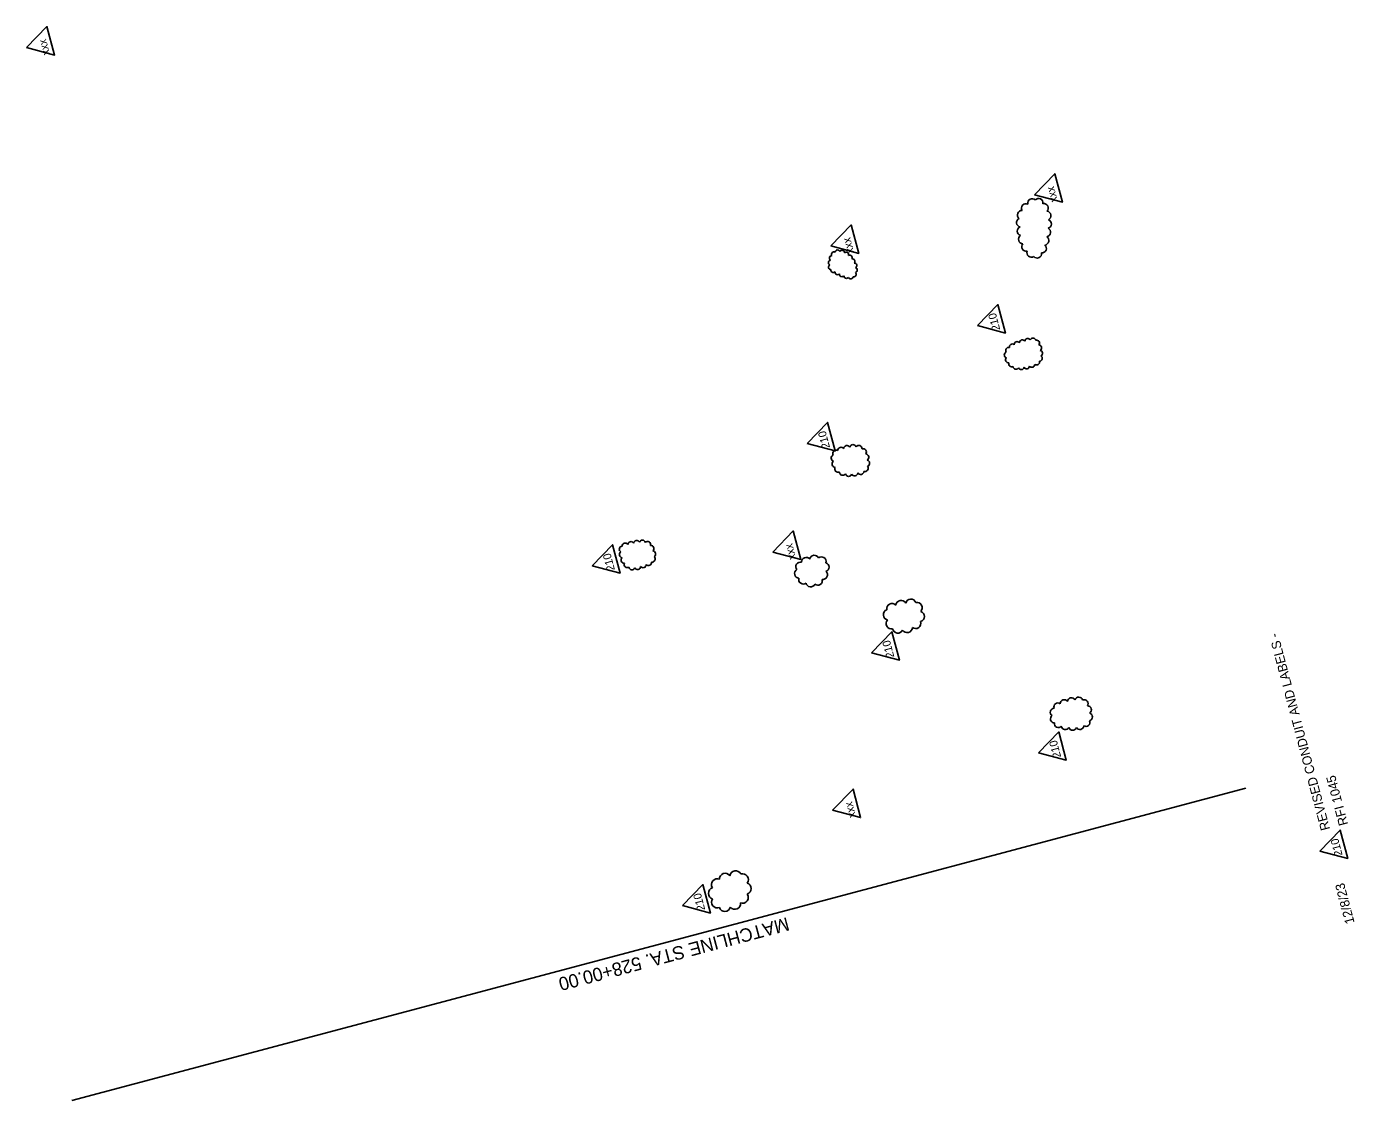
# Model space of a CAD drawing. Extents: x 930124 to 931163, y 628803 to 630086.
# Drawn here: x 930367 to 931163, y 628803 to 629446 of the extents above; entities that cross this region are included whole.
import ezdxf

# ---------------------------------------------------------------- set-up
doc = ezdxf.new("R2010")
doc.units = 0
for name, color, linetype in [('Cloud_dp', 7, 'Continuous'), ('MatchLines_dp', 7, 'Continuous'), ('TextMinor', 7, 'Continuous')]:
    doc.layers.add(name, color=color, linetype=linetype)

msp = doc.modelspace()

# ---------------------------------------------------------------- linework, layer by layer
at = {"layer": 'Cloud_dp'}
for points in [[(930366.73, 629433.4), (930383.48, 629428.93), (930378.95, 629445.99)], [(930970.88, 629345.22), (930987.64, 629340.76), (930983.1, 629357.81)], [(930848.77, 629314.6), (930865.53, 629310.13), (930860.99, 629327.19)], [(930936.68, 629266.85), (930953.44, 629262.39), (930948.9, 629279.45)], [(930834.69, 629196.2), (930851.44, 629191.74), (930846.91, 629208.8)], [(930813.99, 629131.2), (930830.75, 629126.74), (930826.21, 629143.8)], [(930705.73, 629122.9), (930722.49, 629118.44), (930717.95, 629135.5)], [(930873.21, 629070.79), (930889.97, 629066.32), (930885.43, 629083.38)], [(930973.23, 629010.87), (930989.98, 629006.4), (930985.45, 629023.46)], [(930849.92, 628976.57), (930866.67, 628972.11), (930862.14, 628989.17)], [(931141.9, 628952.04), (931158.66, 628947.58), (931154.12, 628964.64)], [(930759.86, 628919.33), (930776.62, 628914.86), (930772.08, 628931.92)]]:
    msp.add_lwpolyline(points, close=True, dxfattribs=at)
for centre, radius, start, end in [((930969.56, 629340.2), 2.69, 47.02622, 192.02622), ((930973.34, 629340.3), 2.69, 351.17918, 136.17918), ((930963.33, 629333.12), 2.69, 85.90866, 230.90866), ((930965.83, 629337.18), 2.69, 65.81449, 210.81449), ((930976.48, 629337.25), 2.69, 315.47406, 100.47406), ((930978.03, 629332.7), 2.69, 297.05766, 82.05766), ((930962.8, 629328.61), 2.69, 115.67642, 260.67642), ((930963.28, 629323.43), 2.69, 109.9098, 254.9098), ((930978.36, 629327.77), 2.69, 285.53496, 70.53496), ((930964.05, 629318.58), 2.69, 123.04285, 268.04285), ((930976.87, 629317.81), 2.69, 273.85274, 58.85274), ((930977.87, 629322.77), 2.69, 278.3399, 63.3399), ((930850.78, 629309.54), 1.51, 64.25659, 209.25659), ((930852.93, 629310.64), 1.51, 25.19628, 170.19628), ((930855.55, 629310.45), 1.51, 1.35126, 146.35126), ((930858.01, 629309.31), 1.51, 343.81258, 128.81258), ((930965.96, 629314.1), 2.69, 138.15829, 283.15829), ((930969.06, 629310.45), 2.69, 157.53748, 302.53748), ((930972.48, 629310.01), 2.69, 222.67057, 7.67057), ((930975.34, 629313.05), 2.69, 265.6604, 50.6604), ((930848.86, 629304.56), 1.51, 99.66415, 244.66415), ((930848.98, 629301.89), 1.51, 120.6446, 265.6446), ((930849.47, 629307.29), 1.51, 90.23348, 235.23348), ((930860.11, 629307.52), 1.51, 330.43389, 115.43389), ((930861.78, 629305.31), 1.51, 318.65228, 103.65228), ((930862.87, 629302.8), 1.51, 303.2417, 88.2417), ((930863.2, 629300.1), 1.51, 285.88168, 70.88168), ((930850.35, 629300.11), 1.51, 169.55406, 314.55406), ((930852.91, 629298.84), 1.51, 172.8068, 317.8068), ((930855.53, 629297.64), 1.51, 172.84611, 317.84611), ((930858.17, 629296.61), 1.51, 179.33238, 324.33238), ((930860.76, 629296.37), 1.51, 205.1875, 350.1875), ((930862.53, 629297.6), 1.51, 259.199, 44.199), ((930957.61, 629254.08), 1.75, 48.74386, 193.74386), ((930960.51, 629255.5), 1.75, 38.60674, 183.60674), ((930963.63, 629256.56), 1.75, 33.64007, 178.64007), ((930966.84, 629257.37), 1.75, 29.72414, 174.72414), ((930970, 629257.61), 1.75, 14.24363, 159.24363), ((930972.16, 629256.36), 1.75, 320.56938, 105.56938), ((930973.42, 629253.5), 1.75, 301.71008, 86.71008), ((930954.57, 629249.23), 1.75, 107.95728, 252.95728), ((930955.3, 629246.32), 1.75, 135.05486, 280.05486), ((930955.4, 629251.98), 1.75, 73.30566, 218.30566), ((930973.8, 629247.21), 1.75, 272.29497, 57.29497), ((930974.02, 629250.28), 1.75, 294.57143, 79.57143), ((930957.2, 629243.87), 1.75, 155.73325, 300.73325), ((930959.84, 629242.44), 1.75, 182.50447, 327.50447), ((930962.93, 629242.2), 1.75, 203.4699, 348.4699), ((930966.16, 629242.73), 1.75, 210.06027, 355.06027), ((930969.33, 629243.6), 1.75, 215.86298, 0.86298), ((930972.19, 629244.99), 1.75, 230.80152, 15.80152), ((930852.06, 629190.25), 1.97, 63.09137, 208.09137), ((930854.93, 629192), 1.97, 34.82572, 179.82572), ((930858.52, 629193), 1.97, 31.3846, 176.3846), ((930862.11, 629193.54), 1.97, 20.56495, 165.56495), ((930865.55, 629193.05), 1.97, 358.34128, 143.34128), ((930868.16, 629191.13), 1.97, 323.83499, 108.83499), ((930850.99, 629187.46), 1.97, 109.87972, 254.87972), ((930851.54, 629183.89), 1.97, 122.75549, 267.75549), ((930869.28, 629181.37), 1.97, 251.31492, 36.31492), ((930869.59, 629188), 1.97, 300.29871, 85.29871), ((930870.14, 629184.37), 1.97, 291.87735, 76.87735), ((930853.16, 629180.91), 1.97, 149.05757, 294.05757), ((930855.94, 629179.11), 1.97, 180.3009, 325.3009), ((930859.47, 629178.48), 1.97, 194.34796, 339.34796), ((930863.05, 629178.74), 1.97, 208.93836, 353.93836), ((930866.68, 629179.59), 1.97, 212.39045, 357.39045), ((930723.9, 629132.9), 1.87, 96.65996, 241.65996), ((930725.56, 629134.69), 1.87, 32.99519, 177.99519), ((930728.98, 629135.57), 1.87, 30.58908, 175.58908), ((930732.44, 629136.21), 1.87, 25.45378, 170.45378), ((930735.9, 629136.44), 1.87, 17.07381, 162.07381), ((930738.93, 629135.59), 1.87, 346.88986, 131.88986), ((930740.9, 629133.31), 1.87, 309.55427, 94.55427), ((930723.96, 629129.65), 1.87, 120.40329, 265.40329), ((930724.99, 629126.34), 1.87, 129.1717, 274.1717), ((930741.63, 629127.01), 1.87, 262.67969, 47.67969), ((930741.94, 629130), 1.87, 300.35633, 85.35633), ((930834.08, 629125.23), 2.76, 39.24013, 184.24013), ((930838.92, 629126.47), 2.76, 24.44248, 169.44248), ((930843.21, 629125.5), 2.76, 345.04943, 130.04943), ((930726.84, 629123.72), 1.87, 156.12895, 301.12895), ((930729.65, 629122.43), 1.87, 189.46548, 334.46548), ((930732.94, 629122.58), 1.87, 210.79964, 355.79964), ((930736.24, 629123.63), 1.87, 219.62405, 4.62405), ((930739.53, 629124.99), 1.87, 220.2265, 5.2265), ((930829.85, 629118.28), 2.76, 121.00696, 266.00696), ((930830.57, 629122.38), 2.76, 74.00552, 219.00552), ((930844.03, 629117.54), 2.76, 261.35818, 46.35818), ((930845.07, 629122.15), 2.76, 288.16799, 73.16799), ((930832.3, 629114.76), 2.75, 163.82406, 308.82406), ((930836.75, 629113.08), 2.76, 189.61657, 334.61657), ((930840.97, 629114.04), 2.76, 231.20098, 16.20098), ((930896.82, 629099.81), 3.19, 21.31159, 166.31159), ((930883.49, 629093.59), 3.19, 110.99142, 255.99142), ((930885.49, 629097.14), 3.19, 45.23836, 190.23836), ((930890.91, 629099.04), 3.19, 28.44484, 173.44484), ((930900.4, 629097.83), 3.19, 315.89591, 100.89591), ((930901.72, 629092.57), 3.19, 287.23506, 72.23506), ((930885.1, 629088.36), 3.19, 138.07375, 283.07375), ((930899.64, 629088.51), 3.19, 233.36669, 18.36669), ((930888.97, 629085.76), 3.19, 189.2824, 334.2824), ((930894.54, 629086.09), 3.19, 212.48287, 357.48287), ((930984.91, 629038.37), 2.4, 53.55366, 198.55366), ((930988.73, 629040.32), 2.4, 35.51001, 180.51001), ((930993.06, 629041.47), 2.4, 29.26426, 174.26426), ((930997.42, 629041.87), 2.4, 16.16228, 161.16228), ((931000.64, 629040.32), 2.4, 327.58751, 112.58751), ((931002.63, 629036.64), 2.4, 304.27582, 89.27582), ((930982.79, 629035.21), 2.4, 93.7819, 238.7819), ((930982.9, 629031.19), 2.4, 124.36294, 269.36294), ((931003.24, 629032.38), 2.4, 286.85619, 71.85619), ((930985.25, 629028.42), 2.4, 171.23084, 316.23084), ((930989.34, 629027.14), 2.4, 188.88447, 333.88447), ((930993.79, 629026.78), 2.4, 196.83582, 341.83582), ((930998.13, 629027.24), 2.4, 210.36256, 355.36256), ((931001.75, 629029.11), 2.4, 239.23599, 24.23599), ((930780.75, 628931.95), 3.47, 68.46599, 213.46599), ((930785.5, 628935.25), 3.47, 36.09124, 181.09124), ((930791.74, 628936.76), 3.47, 26.21778, 171.21778), ((930795.92, 628934.99), 3.47, 322.74245, 107.74245), ((930778.94, 628926.73), 3.47, 108.09552, 253.09552), ((930797.64, 628929.57), 3.47, 287.59727, 72.59727), ((930780.8, 628921.46), 3.47, 145.8684, 290.8684), ((930791.3, 628920.59), 3.47, 220.57779, 5.57779), ((930795.89, 628924.21), 3.47, 251.06604, 36.06604), ((930785.33, 628919.32), 3.47, 198.51028, 343.51028)]:
    msp.add_arc(centre, radius, start, end, dxfattribs=at)
at = {"layer": 'MatchLines_dp'}
msp.add_lwpolyline([(931097.53, 628989.72), (930741.83, 628895.14), (930393.92, 628802.63)], dxfattribs=at)

# ---------------------------------------------------------------- texts
at = {"layer": 'Cloud_dp'}
for s, p in [('xxx', (930380.83, 629429.52)), ('xxx', (930984.99, 629341.34)), ('xxx', (930862.88, 629310.72)), ('210', (930950.4, 629264.44)), ('210', (930848.4, 629193.79)), ('xxx', (930828.1, 629127.32)), ('210', (930719.45, 629120.49)), ('210', (930886.93, 629068.37)), ('210', (930986.94, 629008.45)), ('xxx', (930864.02, 628972.69)), ('210', (931155.62, 628949.63)), ('210', (930773.58, 628916.91))]:
    msp.add_text(s, height=4.799, rotation=104.89046, dxfattribs=at).set_placement(p)
at = {"layer": 'MatchLines_dp'}
msp.add_text('MATCHLINE STA. 528+00.00', height=8, rotation=194.89045, dxfattribs=at).set_placement((930822.6, 628912.48))
at = {"layer": 'TextMinor'}
for s, p in [('REVISED CONDUIT AND LABELS - ', (931148.14, 628965.21)), ('RFI 1045', (931158.97, 628968.09)), ('12/8/23', (931162.84, 628909.17))]:
    msp.add_text(s, height=5.6, rotation=104.89045, dxfattribs=at).set_placement(p)

doc.saveas('drawing.dxf')
